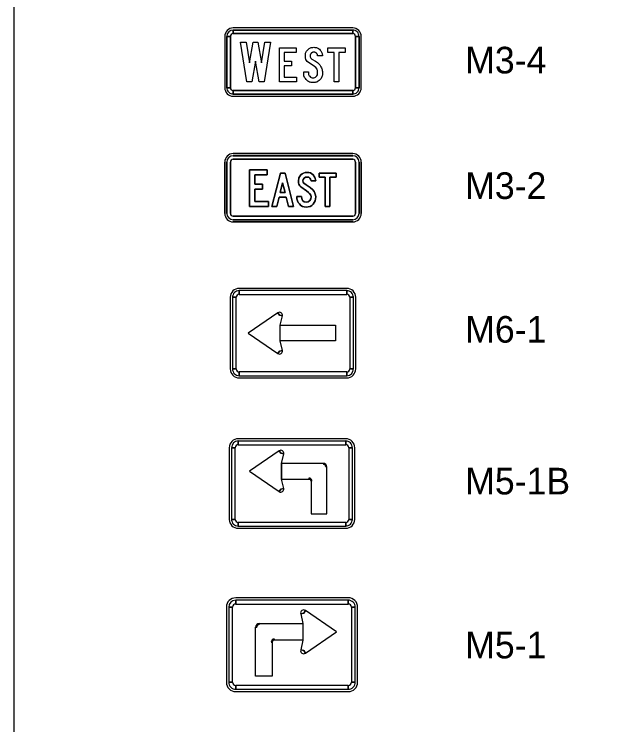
# Model space of a CAD drawing. Extents: x 10133 to 81668, y 5524 to 11018.
# Drawn here: x 35333 to 35778, y 8937 to 9458 of the extents above; entities that cross this region are included whole.
import ezdxf

# ---------------------------------------------------------------- set-up
doc = ezdxf.new("R2010")
doc.units = 0
for name, color, linetype in [('Default', 7, 'Continuous'), ('DisAdjoinersText', 7, 'Continuous'), ('DisCLMLORText', 7, 'Continuous'), ('DisPlatData', 7, 'Continuous'), ('Level 3', 7, 'Continuous'), ('Level 6', 7, 'Continuous')]:
    doc.layers.add(name, color=color, linetype=linetype)

msp = doc.modelspace()

# ---------------------------------------------------------------- linework, layer by layer
at = {"layer": 'Default'}
for p, q in [((35577.16, 9030.02), (35494.74, 9030.02)), ((35494.74, 9025.44), (35494.74, 9028.28)), ((35577.16, 9028.28), (35577.16, 9025.44)), ((35487.87, 9023.15), (35487.87, 8968.2)), ((35489.59, 9023.15), (35492.45, 9023.15)), ((35544.54, 9018.84), (35545.76, 9020.81)), ((35579.45, 9023.15), (35582.31, 9023.15)), ((35584.03, 8968.2), (35584.03, 9023.15)), ((35542.31, 9018.34), (35544.54, 9018.84)), ((35511.91, 9010.37), (35511.91, 9011.15)), ((35509.33, 9008.54), (35510.09, 9008.54)), ((35523.07, 8999.11), (35523.07, 8999.84)), ((35520.64, 8997.42), (35521.35, 8997.42)), ((35544.54, 8991.37), (35542.31, 8991.92)), ((35545.76, 8989.45), (35544.54, 8991.37)), ((35492.45, 8968.2), (35489.59, 8968.2)), ((35494.74, 8963.05), (35494.74, 8965.91)), ((35577.16, 8965.91), (35577.16, 8963.05)), ((35582.31, 8968.2), (35579.45, 8968.2)), ((35494.74, 8961.33), (35577.16, 8961.33))]:
    msp.add_line(p, q, dxfattribs=at)
for points in [[(35577.16, 9028.28), (35494.74, 9028.28), (35494.74, 9025.44), (35577.16, 9025.44), (35577.16, 9028.28)], [(35489.59, 9023.15), (35489.59, 8968.2), (35492.45, 8968.2), (35492.45, 9023.15), (35489.59, 9023.15)], [(35568.58, 9005.11), (35545.76, 9020.81), (35544.54, 9018.84), (35542.31, 9018.34), (35543.96, 9011.15), (35543.96, 8999.11), (35542.31, 8991.92), (35544.54, 8991.37), (35545.76, 8989.45), (35568.58, 9005.11)], [(35582.31, 8968.2), (35582.31, 9023.15), (35579.45, 9023.15), (35579.45, 8968.2), (35582.31, 8968.2)], [(35521.35, 8972.51), (35509.33, 8972.51), (35509.33, 9008.54), (35511.91, 9011.15), (35543.96, 9011.15), (35543.96, 8999.11), (35523.07, 8999.11), (35521.35, 8999.11), (35521.35, 8997.42), (35521.35, 8972.51)], [(35494.74, 8963.05), (35577.16, 8963.05), (35577.16, 8965.91), (35494.74, 8965.91), (35494.74, 8963.05)]]:
    msp.add_lwpolyline(points, close=True, dxfattribs=at)
for centre, radius, start, end in [((35494.74, 9023.15), 6.87, 90.0002, 179.9998), ((35494.74, 9023.15), 5.15, 90.0002, 179.9998), ((35577.16, 9023.15), 6.87, 0, 90.0002), ((35577.16, 9023.15), 5.15, 0, 90.0002), ((35494.74, 9023.15), 2.29, 90.0002, 179.9998), ((35544.54, 9018.84), 2.29, 57.7244, 192.9504), ((35577.16, 9023.15), 2.29, 0, 90.0002), ((35511.91, 9008.54), 2.58, 90.0002, 179.9998), ((35511.91, 9008.54), 1.82, 90.0002, 179.9998), ((35523.07, 8997.42), 2.43, 90.0002, 179.9998), ((35523.07, 8997.42), 1.72, 90.0002, 179.9998), ((35544.54, 8991.37), 2.29, 167.0499, 302.2759), ((35494.74, 8968.2), 6.87, 179.9998, 270.0001), ((35494.74, 8968.2), 5.15, 179.9998, 270.0001), ((35494.74, 8968.2), 2.29, 179.9998, 270.0001), ((35577.16, 8968.2), 6.87, 270.0001, 0.0003), ((35577.16, 8968.2), 5.15, 270.0001, 0.0003), ((35577.16, 8968.2), 2.29, 270.0001, 0.0003)]:
    msp.add_arc(centre, radius, start, end, dxfattribs=at)
at = {"layer": 'DisAdjoinersText'}
for p, q in [((35580.42, 9447.45), (35492.92, 9447.45)), ((35492.92, 9443.28), (35492.92, 9445.89)), ((35492.92, 9445.89), (35580.42, 9445.89)), ((35580.42, 9443.28), (35492.92, 9443.28)), ((35580.42, 9445.89), (35580.42, 9443.28)), ((35486.67, 9441.2), (35486.67, 9403.7)), ((35488.23, 9441.2), (35490.84, 9441.2)), ((35488.23, 9403.7), (35488.23, 9441.2)), ((35490.84, 9441.2), (35490.84, 9403.7)), ((35582.5, 9441.2), (35585.11, 9441.2)), ((35582.5, 9403.7), (35582.5, 9441.2)), ((35585.11, 9441.2), (35585.11, 9403.7)), ((35586.67, 9403.7), (35586.67, 9441.2)), ((35558.24, 9427.03), (35554.71, 9427.03)), ((35551.48, 9420.03), (35548.76, 9421.65)), ((35550.56, 9424.68), (35553.27, 9423.05)), ((35490.84, 9403.7), (35488.23, 9403.7)), ((35492.92, 9399.01), (35492.92, 9401.62)), ((35492.92, 9401.62), (35580.42, 9401.62)), ((35580.42, 9401.62), (35580.42, 9399.01)), ((35585.11, 9403.7), (35582.5, 9403.7)), ((35580.42, 9399.01), (35492.92, 9399.01)), ((35492.92, 9397.45), (35580.42, 9397.45))]:
    msp.add_line(p, q, dxfattribs=at)
for points in [[(35580.42, 9445.89), (35492.92, 9445.89), (35492.92, 9443.28), (35580.42, 9443.28), (35580.42, 9445.89), (35580.42, 9445.89)], [(35488.23, 9441.2), (35488.23, 9403.7), (35490.84, 9403.7), (35490.84, 9441.2), (35488.23, 9441.2), (35488.23, 9441.2)], [(35585.11, 9403.7), (35585.11, 9441.2), (35582.5, 9441.2), (35582.5, 9403.7), (35585.11, 9403.7), (35585.11, 9403.7)], [(35492.92, 9399.01), (35580.42, 9399.01), (35580.42, 9401.62), (35492.92, 9401.62), (35492.92, 9399.01), (35492.92, 9399.01)]]:
    msp.add_lwpolyline(points, close=True, dxfattribs=at)
for points in [[(35516.02, 9437.06), (35520.16, 9437.06), (35515.61, 9407.87), (35511.96, 9407.87), (35509.22, 9423.13), (35506.47, 9407.87), (35502.83, 9407.87), (35498.27, 9437.06), (35502.42, 9437.06), (35504.81, 9421.82), (35507.53, 9437.06), (35510.91, 9437.06), (35513.63, 9421.82), (35516.02, 9437.06)], [(35516.02, 9437.06), (35520.16, 9437.06), (35515.61, 9407.87), (35511.96, 9407.87), (35509.22, 9423.13), (35506.47, 9407.87), (35502.83, 9407.87), (35498.27, 9437.06), (35502.42, 9437.06), (35504.81, 9421.82), (35507.53, 9437.06), (35510.91, 9437.06), (35513.63, 9421.82), (35516.02, 9437.06)], [(35539.3, 9411.4), (35539.3, 9407.87), (35526.78, 9407.87), (35526.78, 9432.89), (35538.9, 9432.89), (35538.9, 9429.36), (35530.32, 9429.36), (35530.32, 9423.1), (35535.59, 9423.1), (35535.59, 9419.6), (35530.32, 9419.6), (35530.32, 9411.4), (35539.3, 9411.4)], [(35539.3, 9411.4), (35539.3, 9407.87), (35526.78, 9407.87), (35526.78, 9432.89), (35538.9, 9432.89), (35538.9, 9429.36), (35530.32, 9429.36), (35530.32, 9423.1), (35535.59, 9423.1), (35535.59, 9419.6), (35530.32, 9419.6), (35530.32, 9411.4), (35539.3, 9411.4)], [(35574.82, 9432.89), (35574.82, 9429.56), (35570.31, 9429.56), (35570.31, 9407.87), (35566.82, 9407.87), (35566.82, 9429.56), (35562.31, 9429.56), (35562.31, 9432.89), (35574.82, 9432.89)], [(35574.82, 9432.89), (35574.82, 9429.56), (35570.31, 9429.56), (35570.31, 9407.87), (35566.82, 9407.87), (35566.82, 9429.56), (35562.31, 9429.56), (35562.31, 9432.89), (35574.82, 9432.89)], [(35558.24, 9427.03), (35554.71, 9427.03)], [(35551.48, 9420.03), (35548.76, 9421.65)], [(35550.56, 9424.68), (35553.27, 9423.05)], [(35544.55, 9414.3), (35544.55, 9415.3), (35548.08, 9415.3), (35548.08, 9414.32)], [(35544.55, 9414.3), (35544.55, 9415.3), (35548.08, 9415.3), (35548.08, 9414.32)]]:
    msp.add_lwpolyline(points, dxfattribs=at)
for centre, radius, start, end in [((35492.92, 9441.2), 6.25, 90.0002, 179.9998), ((35580.42, 9441.2), 6.25, 360, 90.0002), ((35492.92, 9441.2), 4.69, 90.0002, 179.9998), ((35492.92, 9441.2), 4.69, 90.0002, 179.9998), ((35492.92, 9441.2), 2.08, 90.0002, 179.9998), ((35492.92, 9441.2), 2.08, 90.0002, 179.9998), ((35580.42, 9441.2), 4.69, 360, 90.0002), ((35580.42, 9441.2), 4.69, 360, 90.0002), ((35580.42, 9441.2), 2.08, 0, 90.0002), ((35580.42, 9441.2), 2.08, 0, 90.0002), ((35492.92, 9403.7), 6.25, 179.9998, 270.0001), ((35492.92, 9403.7), 4.69, 179.9998, 270.0001), ((35492.92, 9403.7), 4.69, 179.9998, 270.0001), ((35492.92, 9403.7), 2.08, 179.9998, 270.0001), ((35492.92, 9403.7), 2.08, 179.9998, 270.0001), ((35580.42, 9403.7), 4.69, 270.0001, 0.0003), ((35580.42, 9403.7), 2.08, 270.0001, 0.0003), ((35580.42, 9403.7), 6.25, 270.0001, 0.0003), ((35580.42, 9403.7), 4.69, 270.0001, 0.0003), ((35580.42, 9403.7), 2.08, 270.0001, 0.0003)]:
    msp.add_arc(centre, radius, start, end, dxfattribs=at)
for points in [[(35548.76, 9421.65), (35545.73, 9423.45), (35545.73, 9427.03), (35545.73, 9429.61), (35547.56, 9431.44), (35549.38, 9433.26), (35551.99, 9433.26), (35554.57, 9433.26), (35556.39, 9431.44), (35558.24, 9429.58), (35558.24, 9427.03)], [(35548.76, 9421.65), (35545.73, 9423.45), (35545.73, 9427.03), (35545.73, 9429.61), (35547.56, 9431.44), (35549.38, 9433.26), (35551.99, 9433.26), (35554.57, 9433.26), (35556.39, 9431.44), (35558.24, 9429.58), (35558.24, 9427.03)], [(35554.71, 9427.03), (35554.71, 9427.58), (35554.5, 9428.08), (35554.29, 9428.58), (35553.91, 9428.96), (35553.54, 9429.33), (35553.04, 9429.55), (35552.54, 9429.76), (35551.99, 9429.76), (35551.41, 9429.76), (35550.92, 9429.55), (35550.44, 9429.33), (35550.06, 9428.96), (35549.69, 9428.58), (35549.47, 9428.08), (35549.26, 9427.58), (35549.26, 9427.03), (35549.26, 9425.46), (35550.56, 9424.68)], [(35554.71, 9427.03), (35554.71, 9427.58), (35554.5, 9428.08), (35554.29, 9428.58), (35553.91, 9428.96), (35553.54, 9429.33), (35553.04, 9429.55), (35552.54, 9429.76), (35551.99, 9429.76), (35551.41, 9429.76), (35550.92, 9429.55), (35550.44, 9429.33), (35550.06, 9428.96), (35549.69, 9428.58), (35549.47, 9428.08), (35549.26, 9427.58), (35549.26, 9427.03), (35549.26, 9425.46), (35550.56, 9424.68)], [(35553.27, 9423.05), (35555.57, 9421.65), (35556.87, 9419.4), (35558.24, 9417.05), (35558.24, 9414.32), (35558.24, 9411.52), (35556.24, 9409.47), (35554.26, 9407.49), (35551.39, 9407.49), (35548.53, 9407.49), (35546.55, 9409.47), (35544.55, 9411.47), (35544.55, 9414.3)], [(35553.27, 9423.05), (35555.57, 9421.65), (35556.87, 9419.4), (35558.24, 9417.05), (35558.24, 9414.32), (35558.24, 9411.52), (35556.24, 9409.47), (35554.26, 9407.49), (35551.39, 9407.49), (35548.53, 9407.49), (35546.55, 9409.47), (35544.55, 9411.47), (35544.55, 9414.3)], [(35548.08, 9414.32), (35548.08, 9412.97), (35549.03, 9411.97), (35550.01, 9410.99), (35551.39, 9410.99), (35552.76, 9410.99), (35553.74, 9411.97), (35554.71, 9412.95), (35554.71, 9414.32), (35554.71, 9418.1), (35551.48, 9420.03)], [(35548.08, 9414.32), (35548.08, 9412.97), (35549.03, 9411.97), (35550.01, 9410.99), (35551.39, 9410.99), (35552.76, 9410.99), (35553.74, 9411.97), (35554.71, 9412.95), (35554.71, 9414.32), (35554.71, 9418.1), (35551.48, 9420.03)]]:
    msp.add_open_spline(points, degree=3, dxfattribs=at)
at = {"layer": 'DisPlatData'}
for p, q in [((35492.92, 9355.41), (35580.42, 9355.41)), ((35580.42, 9355.41), (35492.92, 9355.41)), ((35492.92, 9355.41), (35492.92, 9355.41)), ((35492.92, 9355.41), (35492.92, 9355.41)), ((35492.92, 9355.41), (35580.42, 9355.41)), ((35580.42, 9355.41), (35492.92, 9355.41)), ((35580.42, 9353.85), (35492.92, 9353.85)), ((35492.92, 9353.85), (35492.92, 9353.85)), ((35492.92, 9353.85), (35580.42, 9353.85)), ((35580.42, 9355.41), (35580.42, 9355.41)), ((35580.42, 9355.41), (35580.42, 9355.41)), ((35486.67, 9349.16), (35486.67, 9349.16)), ((35486.67, 9311.66), (35486.67, 9349.16)), ((35486.67, 9349.16), (35486.67, 9349.16)), ((35486.67, 9349.16), (35486.67, 9311.66)), ((35486.67, 9311.66), (35486.67, 9349.16)), ((35486.67, 9349.16), (35486.67, 9311.66)), ((35488.23, 9349.16), (35488.23, 9349.16)), ((35488.23, 9349.16), (35488.23, 9311.66)), ((35488.23, 9311.66), (35488.23, 9349.16)), ((35490.84, 9311.66), (35490.84, 9349.16)), ((35490.84, 9349.16), (35490.84, 9349.16)), ((35490.84, 9349.16), (35490.84, 9311.66)), ((35492.92, 9351.24), (35492.92, 9351.24)), ((35492.92, 9351.24), (35580.42, 9351.24)), ((35580.42, 9351.24), (35492.92, 9351.24)), ((35582.5, 9349.16), (35582.5, 9311.66)), ((35582.5, 9311.66), (35582.5, 9349.16)), ((35585.11, 9311.66), (35585.11, 9349.16)), ((35585.11, 9349.16), (35585.11, 9311.66)), ((35586.67, 9349.16), (35586.67, 9349.16)), ((35586.67, 9349.16), (35586.67, 9311.66)), ((35586.67, 9311.66), (35586.67, 9349.16)), ((35586.67, 9349.16), (35586.67, 9349.16)), ((35586.67, 9349.16), (35586.67, 9311.66)), ((35586.67, 9311.66), (35586.67, 9349.16)), ((35486.67, 9311.66), (35486.67, 9311.66)), ((35486.67, 9311.66), (35486.67, 9311.66)), ((35580.42, 9309.58), (35492.92, 9309.58)), ((35492.92, 9309.58), (35580.42, 9309.58)), ((35492.92, 9306.97), (35580.42, 9306.97)), ((35580.42, 9306.97), (35492.92, 9306.97)), ((35580.42, 9309.58), (35580.42, 9309.58)), ((35580.42, 9306.97), (35580.42, 9306.97)), ((35586.67, 9311.66), (35586.67, 9311.66)), ((35586.67, 9311.66), (35586.67, 9311.66)), ((35492.92, 9305.41), (35492.92, 9305.41)), ((35580.42, 9305.41), (35492.92, 9305.41)), ((35492.92, 9305.41), (35492.92, 9305.41)), ((35492.92, 9305.41), (35580.42, 9305.41)), ((35580.42, 9305.41), (35492.92, 9305.41)), ((35492.92, 9305.41), (35580.42, 9305.41)), ((35580.42, 9305.41), (35580.42, 9305.41)), ((35580.42, 9305.41), (35580.42, 9305.41))]:
    msp.add_line(p, q, dxfattribs=at)
for points in [[(35518.72, 9320.36), (35508.79, 9320.36), (35508.79, 9329.35), (35514.42, 9329.35), (35514.42, 9333.05), (35508.79, 9333.05), (35508.79, 9339.93), (35517.69, 9339.93), (35517.69, 9343.63), (35504.85, 9343.63), (35504.85, 9316.66), (35518.72, 9316.66), (35518.72, 9320.36)], [(35518.72, 9316.66), (35504.85, 9316.66), (35504.85, 9343.63), (35517.69, 9343.63), (35517.69, 9339.93), (35508.79, 9339.93), (35508.79, 9333.05), (35514.42, 9333.05), (35514.42, 9329.35), (35508.79, 9329.35), (35508.79, 9320.36), (35518.72, 9320.36), (35518.72, 9316.66)], [(35521.24, 9316.66), (35524.8, 9316.66), (35526.46, 9323.41), (35531.75, 9323.41), (35533.48, 9316.66), (35537.06, 9316.66), (35530.88, 9341.18), (35527.42, 9341.18), (35521.24, 9316.66)], [(35527.42, 9341.18), (35530.88, 9341.18), (35537.06, 9316.66), (35533.48, 9316.66), (35531.75, 9323.41), (35526.46, 9323.41), (35524.8, 9316.66), (35521.24, 9316.66), (35527.42, 9341.18)], [(35539.49, 9324.03), (35539.49, 9323.8), (35539.59, 9322.31), (35539.95, 9320.93), (35540.55, 9319.66), (35541.39, 9318.5), (35542.45, 9317.48), (35543.65, 9316.76), (35544.97, 9316.32), (35546.43, 9316.18), (35547.89, 9316.31), (35549.22, 9316.74), (35550.4, 9317.44), (35551.45, 9318.43), (35552.27, 9319.56), (35552.86, 9320.82), (35553.21, 9322.18), (35553.33, 9323.67), (35553.19, 9325.08), (35552.78, 9326.44), (35552.09, 9327.72), (35551.13, 9328.92), (35549.28, 9330.52), (35546.43, 9332.47), (35544.55, 9333.88), (35544.15, 9334.6), (35544.01, 9335.42), (35544.23, 9336.51), (35544.89, 9337.44), (35545.84, 9338.06), (35546.98, 9338.27), (35548.19, 9338.07), (35549.08, 9337.48), (35549.56, 9336.65), (35549.92, 9335.42), (35553.33, 9335.42), (35552.78, 9337.92), (35551.48, 9339.89), (35550.52, 9340.66), (35549.45, 9341.21), (35548.22, 9341.55), (35546.88, 9341.66), (35545.63, 9341.54), (35544.48, 9341.18), (35543.42, 9340.59), (35542.45, 9339.76), (35541.06, 9337.71), (35540.6, 9335.32), (35540.71, 9334.08), (35541.06, 9332.96), (35541.65, 9331.91), (35542.48, 9330.97), (35546.46, 9328.12), (35547.94, 9327), (35548.85, 9326.16), (35549.67, 9324.94), (35549.94, 9323.63), (35549.7, 9322.18), (35549, 9320.95), (35547.85, 9320.05), (35546.43, 9319.74), (35544.93, 9320.08), (35543.76, 9321.08), (35543.08, 9322.42), (35542.88, 9324.03), (35539.49, 9324.03)], [(35542.88, 9324.03), (35543.08, 9322.42), (35543.76, 9321.08), (35544.93, 9320.08), (35546.43, 9319.74), (35547.85, 9320.05), (35549, 9320.95), (35549.7, 9322.18), (35549.94, 9323.63), (35549.67, 9324.94), (35548.85, 9326.16), (35547.94, 9327), (35546.46, 9328.12), (35542.48, 9330.97), (35541.65, 9331.91), (35541.06, 9332.96), (35540.71, 9334.08), (35540.6, 9335.32), (35541.06, 9337.71), (35542.45, 9339.76), (35543.42, 9340.59), (35544.48, 9341.18), (35545.63, 9341.54), (35546.88, 9341.66), (35548.22, 9341.55), (35549.45, 9341.21), (35550.52, 9340.66), (35551.48, 9339.89), (35552.78, 9337.92), (35553.33, 9335.42), (35549.92, 9335.42), (35549.56, 9336.65), (35549.08, 9337.48), (35548.19, 9338.07), (35546.98, 9338.27), (35545.84, 9338.06), (35544.89, 9337.44), (35544.23, 9336.51), (35544.01, 9335.42), (35544.15, 9334.6), (35544.55, 9333.88), (35546.43, 9332.47), (35549.28, 9330.52), (35551.13, 9328.92), (35552.09, 9327.72), (35552.78, 9326.44), (35553.19, 9325.08), (35553.33, 9323.67), (35553.21, 9322.18), (35552.86, 9320.82), (35552.27, 9319.56), (35551.45, 9318.43), (35550.4, 9317.44), (35549.22, 9316.74), (35547.89, 9316.31), (35546.43, 9316.18), (35544.97, 9316.32), (35543.65, 9316.76), (35542.45, 9317.48), (35541.39, 9318.5), (35540.55, 9319.66), (35539.95, 9320.93), (35539.59, 9322.31), (35539.49, 9323.8), (35539.49, 9324.03), (35542.88, 9324.03)], [(35560.22, 9316.66), (35563.77, 9316.66), (35563.77, 9338.1), (35568.35, 9338.1), (35568.35, 9341.18), (35555.74, 9341.18), (35555.74, 9338.1), (35560.22, 9338.1), (35560.22, 9316.66)], [(35560.22, 9338.1), (35555.74, 9338.1), (35555.74, 9341.18), (35568.35, 9341.18), (35568.35, 9338.1), (35563.77, 9338.1), (35563.77, 9316.66), (35560.22, 9316.66), (35560.22, 9338.1)], [(35527.32, 9326.9), (35529.05, 9334.02), (35530.88, 9326.9), (35527.32, 9326.9)], [(35530.88, 9326.9), (35529.05, 9334.02), (35527.32, 9326.9), (35530.88, 9326.9)]]:
    msp.add_lwpolyline(points, dxfattribs=at)
for centre, radius, start, end in [((35492.92, 9349.16), 6.25, 90.0002, 179.9998), ((35492.92, 9349.16), 6.25, 90.0002, 179.9998), ((35492.92, 9349.16), 6.25, 90.0002, 179.9998), ((35492.92, 9349.16), 6.25, 90.0002, 179.9998), ((35492.92, 9349.16), 4.69, 90.0002, 179.9998), ((35492.92, 9349.16), 4.69, 90.0002, 179.9998), ((35580.42, 9349.16), 6.25, 0, 90.0002), ((35580.42, 9349.16), 6.25, 0, 90.0002), ((35580.42, 9349.16), 6.25, 0, 90.0002), ((35580.42, 9349.16), 6.25, 0, 90.0002), ((35580.42, 9349.16), 4.69, 0, 90), ((35580.42, 9349.16), 4.69, 0, 90), ((35492.92, 9349.16), 2.08, 90.0002, 179.9998), ((35492.92, 9349.16), 2.08, 90.0002, 179.9998), ((35580.42, 9349.16), 2.08, 0, 90), ((35580.42, 9349.16), 2.08, 0, 90), ((35492.92, 9311.66), 6.25, 179.9998, 270.0001), ((35492.92, 9311.66), 6.25, 179.9998, 270.0001), ((35492.92, 9311.66), 6.25, 179.9998, 270.0001), ((35492.92, 9311.66), 6.25, 179.9998, 270.0001), ((35492.92, 9311.66), 4.69, 180, 270), ((35492.92, 9311.66), 4.69, 180, 270), ((35492.92, 9311.66), 2.08, 180, 270), ((35492.92, 9311.66), 2.08, 180, 270), ((35580.42, 9311.66), 6.25, 270.0001, 0.0003), ((35580.42, 9311.66), 6.25, 270.0001, 0.0003), ((35580.42, 9311.66), 6.25, 270.0001, 0.0003), ((35580.42, 9311.66), 4.69, 270.0001, 0), ((35580.42, 9311.66), 2.08, 270.0001, 0), ((35580.42, 9311.66), 6.25, 270.0001, 0.0003), ((35580.42, 9311.66), 4.69, 270.0001, 0), ((35580.42, 9311.66), 2.08, 270.0001, 0)]:
    msp.add_arc(centre, radius, start, end, dxfattribs=at)
at = {"layer": 'Level 3'}
msp.add_lwpolyline([(35332.52, 9944.02), (38467.53, 9944.02), (38467.53, 7924.02), (35332.52, 7924.02)], close=True, dxfattribs=at)
at = {"layer": 'Level 6'}
for p, q in [((35576.04, 9256.7), (35497.3, 9256.7)), ((35497.3, 9252.32), (35497.3, 9255.04)), ((35576.04, 9255.04), (35576.04, 9252.32)), ((35490.74, 9250.14), (35490.74, 9197.64)), ((35492.38, 9250.14), (35495.11, 9250.14)), ((35578.23, 9250.14), (35580.96, 9250.14)), ((35582.6, 9197.64), (35582.6, 9250.14)), ((35525.66, 9238.85), (35526.83, 9237.01)), ((35526.83, 9237.01), (35528.96, 9236.53)), ((35526.83, 9210.76), (35525.66, 9208.93)), ((35528.96, 9211.25), (35526.83, 9210.76)), ((35495.11, 9197.64), (35492.38, 9197.64)), ((35580.96, 9197.64), (35578.23, 9197.64)), ((35497.3, 9192.74), (35497.3, 9195.45)), ((35576.04, 9195.45), (35576.04, 9192.74)), ((35497.3, 9191.08), (35576.04, 9191.08)), ((35575.32, 9146.56), (35496.58, 9146.56)), ((35496.58, 9142.18), (35496.58, 9144.89)), ((35575.32, 9144.89), (35575.32, 9142.18)), ((35490.02, 9139.99), (35490.02, 9087.5)), ((35491.66, 9139.99), (35494.39, 9139.99)), ((35526.58, 9137.76), (35527.75, 9135.88)), ((35527.75, 9135.88), (35529.88, 9135.4)), ((35577.51, 9139.99), (35580.24, 9139.99)), ((35581.88, 9087.5), (35581.88, 9139.99)), ((35558.92, 9128.53), (35558.92, 9127.79)), ((35560.66, 9126.04), (35561.38, 9126.04)), ((35548.26, 9117.73), (35548.26, 9117.03)), ((35549.9, 9115.41), (35550.57, 9115.41)), ((35527.75, 9109.63), (35526.58, 9107.8)), ((35529.88, 9110.16), (35527.75, 9109.63)), ((35494.39, 9087.5), (35491.66, 9087.5)), ((35496.58, 9082.58), (35496.58, 9085.31)), ((35575.32, 9085.31), (35575.32, 9082.58)), ((35580.24, 9087.5), (35577.51, 9087.5)), ((35496.58, 9080.94), (35575.32, 9080.94))]:
    msp.add_line(p, q, dxfattribs=at)
for points in [[(35576.04, 9255.04), (35497.3, 9255.04), (35497.3, 9252.32), (35576.04, 9252.32), (35576.04, 9255.04)], [(35492.38, 9250.14), (35492.38, 9197.64), (35495.11, 9197.64), (35495.11, 9250.14), (35492.38, 9250.14)], [(35580.96, 9197.64), (35580.96, 9250.14), (35578.23, 9250.14), (35578.23, 9197.64), (35580.96, 9197.64)], [(35503.86, 9223.89), (35525.66, 9208.93), (35526.83, 9210.76), (35528.96, 9211.25), (35527.37, 9218.16), (35527.37, 9229.62), (35528.96, 9236.53), (35526.83, 9237.01), (35525.66, 9238.85), (35503.86, 9223.89)], [(35567.84, 9229.62), (35567.84, 9218.16), (35527.37, 9218.16), (35527.37, 9229.62), (35567.84, 9229.62)], [(35497.3, 9192.74), (35576.04, 9192.74), (35576.04, 9195.45), (35497.3, 9195.45), (35497.3, 9192.74)], [(35575.32, 9144.89), (35496.58, 9144.89), (35496.58, 9142.18), (35575.32, 9142.18), (35575.32, 9144.89)], [(35491.66, 9139.99), (35491.66, 9087.5), (35494.39, 9087.5), (35494.39, 9139.99), (35491.66, 9139.99)], [(35504.78, 9122.76), (35526.58, 9107.8), (35527.75, 9109.63), (35529.88, 9110.16), (35528.29, 9117.03), (35528.29, 9128.53), (35529.88, 9135.4), (35527.75, 9135.88), (35526.58, 9137.76), (35504.78, 9122.76)], [(35580.24, 9087.5), (35580.24, 9139.99), (35577.51, 9139.99), (35577.51, 9087.5), (35580.24, 9087.5)], [(35549.9, 9091.61), (35561.38, 9091.61), (35561.38, 9126.04), (35558.92, 9128.53), (35528.29, 9128.53), (35528.29, 9117.03), (35548.26, 9117.03), (35549.9, 9117.03), (35549.9, 9115.41), (35549.9, 9091.61)], [(35496.58, 9082.58), (35575.32, 9082.58), (35575.32, 9085.31), (35496.58, 9085.31), (35496.58, 9082.58)]]:
    msp.add_lwpolyline(points, close=True, dxfattribs=at)
for centre, radius, start, end in [((35497.3, 9250.14), 6.56, 90.0001, 180.0003), ((35497.3, 9250.14), 4.92, 90.0001, 180.0003), ((35576.04, 9250.14), 6.56, 359.9998, 90.0001), ((35576.04, 9250.14), 4.92, 359.9998, 90.0001), ((35497.3, 9250.14), 2.19, 90.0001, 180.0003), ((35576.04, 9250.14), 2.19, 359.9998, 90.0001), ((35526.83, 9237.01), 2.19, 347.0499, 122.2759), ((35526.83, 9210.76), 2.19, 237.7244, 12.9504), ((35497.3, 9197.64), 6.56, 180, 270.0002), ((35497.3, 9197.64), 4.92, 180, 270.0002), ((35497.3, 9197.64), 2.19, 180, 270.0002), ((35576.04, 9197.64), 6.56, 270.0002, 359.9998), ((35576.04, 9197.64), 4.92, 270.0002, 359.9998), ((35576.04, 9197.64), 2.19, 270.0002, 359.9998), ((35496.58, 9139.99), 6.56, 90.0002, 179.9998), ((35575.32, 9139.99), 6.56, 0, 90.0002), ((35496.58, 9139.99), 4.92, 90.0002, 179.9998), ((35496.58, 9139.99), 2.19, 90.0002, 179.9998), ((35575.32, 9139.99), 4.92, 0, 90.0002), ((35575.32, 9139.99), 2.19, 0, 90.0002), ((35527.75, 9135.88), 2.19, 347.0497, 122.2758), ((35558.92, 9126.04), 2.46, 0, 90.0002), ((35558.92, 9126.04), 1.74, 0, 90.0002), ((35548.26, 9115.41), 2.32, 0, 90.0002), ((35548.26, 9115.41), 1.64, 0, 90.0002), ((35527.75, 9109.63), 2.19, 237.7242, 12.9503), ((35496.58, 9087.5), 6.56, 179.9998, 270.0001), ((35496.58, 9087.5), 4.92, 179.9998, 270.0001), ((35496.58, 9087.5), 2.19, 179.9998, 270.0001), ((35575.32, 9087.5), 6.56, 270.0001, 0.0003), ((35575.32, 9087.5), 4.92, 270.0001, 0.0003), ((35575.32, 9087.5), 2.19, 270.0001, 0.0003)]:
    msp.add_arc(centre, radius, start, end, dxfattribs=at)

# ---------------------------------------------------------------- texts
at = {"layer": 'DisCLMLORText'}
for s, p in [('M3-4', (35662.81, 9414.14)), ('M3-2', (35662.81, 9322.18)), ('M6-1', (35662.81, 9216.93)), ('M5-1B', (35662.81, 9105.76)), ('M5-1', (35662.81, 8985.66))]:
    msp.add_text(s, height=19.507, dxfattribs=at).set_placement(p)

doc.saveas('drawing.dxf')
